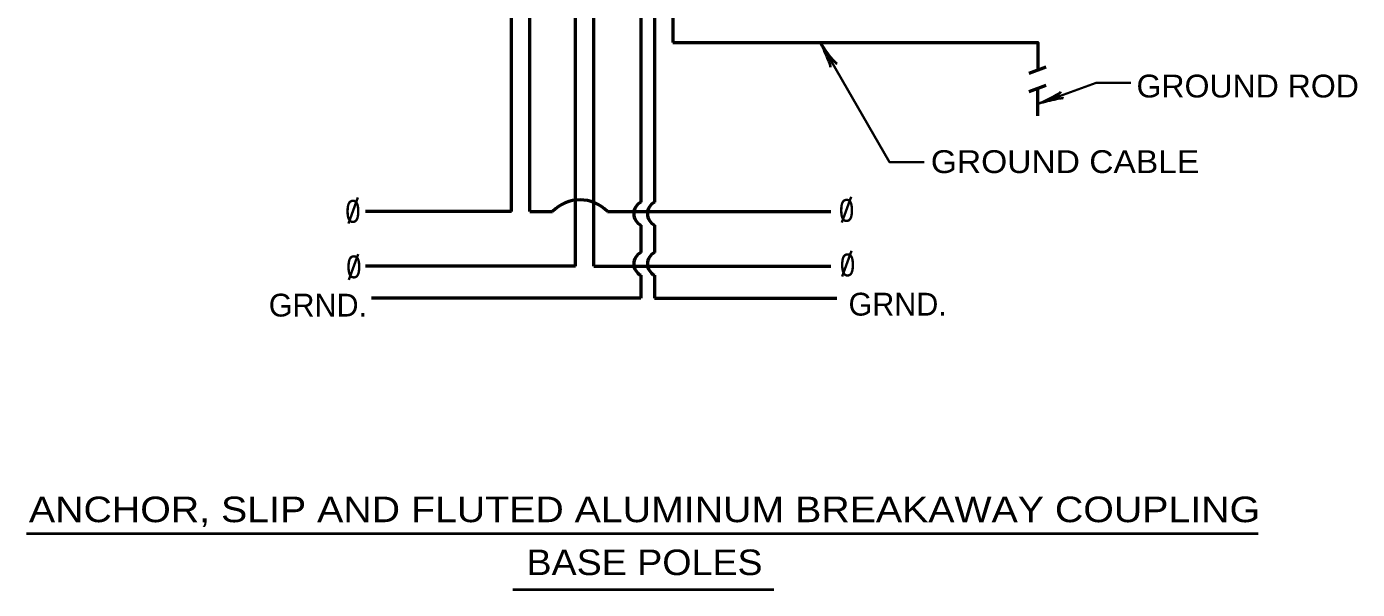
# Model space of a CAD drawing. Extents: x -217 to 639, y -295 to 249.
# Drawn here: x -124 to 51, y 10 to 84 of the extents above; entities that cross this region are included whole.
import ezdxf
from ezdxf.enums import TextEntityAlignment as Align

# ---------------------------------------------------------------- set-up
doc = ezdxf.new("R2010")
doc.units = 0
doc.header["$LTSCALE"] = 1.2
doc.layers.add('1', color=7, linetype='Continuous', lineweight=53)

msp = doc.modelspace()

# ---------------------------------------------------------------- linework, layer by layer
at = {"layer": '1'}
for p, q in [((-60.206, 59.679), (-60.206, 108.564)), ((-57.806, 59.679), (-57.806, 108.564)), ((-51.806, 52.479), (-51.806, 108.564)), ((-49.406, 52.479), (-49.406, 108.564)), ((-43.214, 93.277), (-43.214, 60.877)), ((-41.414, 93.277), (-41.414, 60.877)), ((-39.014, 94.477), (-39.014, 81.877)), ((7.858, 77.867), (10.114, 78.688)), ((7.858, 75.467), (10.114, 76.288)), ((8.968, 75.848), (8.968, 72.248)), ((-60.206, 59.679), (-79.406, 59.679)), ((-57.806, 59.679), (-54.806, 59.679)), ((-47.606, 59.679), (-18.206, 59.679)), ((-43.214, 57.877), (-43.214, 54.277)), ((-41.414, 57.877), (-41.414, 54.277)), ((-51.806, 52.479), (-79.406, 52.479)), ((-49.406, 52.479), (-18.206, 52.479)), ((-43.214, 51.277), (-43.214, 48.277)), ((-41.414, 51.277), (-41.414, 48.277)), ((-43.214, 48.277), (-78.614, 48.277)), ((-41.414, 48.277), (-17.414, 48.277))]:
    msp.add_line(p, q, dxfattribs=at)
at = {"layer": '1', "lineweight": 35}
for p, q in [((-80.441, 61.503), (-81.678, 58.104)), ((-15.543, 61.6), (-16.78, 58.201)), ((-15.494, 54.503), (-16.732, 51.103)), ((-80.392, 54.065), (-81.63, 50.666))]:
    msp.add_line(p, q, dxfattribs=at)
at = {"layer": '1', "lineweight": 40}
for p, q in [((-123.991, 17.293), (37.962, 17.293)), ((-60.032, 9.958), (-25.703, 9.958))]:
    msp.add_line(p, q, dxfattribs=at)
at = {"layer": '1'}
msp.add_lwpolyline([(-39.014, 81.877), (8.986, 81.877), (8.986, 78.277)], dxfattribs=at)
at = {"layer": '1', "lineweight": 35}
for points in [[(-5.952, 66.16), (-10.51, 66.16), (-19.584, 81.877)], [(21.228, 76.604), (16.67, 76.604), (8.968, 73.801)]]:
    msp.add_lwpolyline(points, dxfattribs=at)
at = {"layer": '1'}
for centre, radius, start, end in [((-51.206, 56.164), 5.031, 44.3118, 135.68821), ((-42.45, 59.377), 1.683, 116.97883, 243.02117), ((-40.65, 59.377), 1.683, 116.97883, 243.02117), ((-42.45, 52.777), 1.683, 116.97883, 243.02117), ((-40.65, 52.777), 1.683, 116.97883, 243.02117)]:
    msp.add_arc(centre, radius, start, end, dxfattribs=at)
at = {"layer": '1', "lineweight": 40}
for centre, major_axis, ratio, start_param, end_param in [((-19.131, 80.586), (-0.871, 1.931), 0.07063, 3.1407148, 5.41811), ((-18.642, 80.909), (-1.234, 1.762), 0.122415, 0.8963533, 3.1415927), ((10.085, 74.56), (-1.95, -0.909), 0.122415, 0.8963533, 3.1415927), ((10.318, 74.022), (2.053, 0.523), 0.07063, 6.2823074, 8.5597026)]:
    msp.add_ellipse(centre, major_axis=major_axis, ratio=ratio, start_param=start_param, end_param=end_param, dxfattribs=at)

# ---------------------------------------------------------------- texts
at = {"layer": '1'}
for s, width, p in [('GROUND ROD', 1.05, (21.983, 74.664)), ('GROUND CABLE', 1.1, (-5.071, 64.723)), ('0', 0.9, (-17.151, 58.306)), ('0', 0.9, (-82.079, 58.18)), ('0', 0.9, (-81.953, 50.882)), ('0', 0.9, (-17.025, 51.134))]:
    msp.add_text(s, height=3, dxfattribs=dict(at, width=width)).set_placement(p)
for p in [(-15.892, 45.974), (-92.145, 45.849)]:
    msp.add_text('GRND.', height=3, dxfattribs=at).set_placement(p)
for s, width, p in [('ANCHOR, SLIP AND FLUTED ALUMINUM BREAKAWAY COUPLING', 1.15, (-42.722, 18.799)), ('BASE POLES', 1.1, (-42.721, 11.839))]:
    msp.add_text(s, height=3.36, dxfattribs=dict(at, width=width)).set_placement(p, align=Align.CENTER)

doc.saveas('drawing.dxf')
